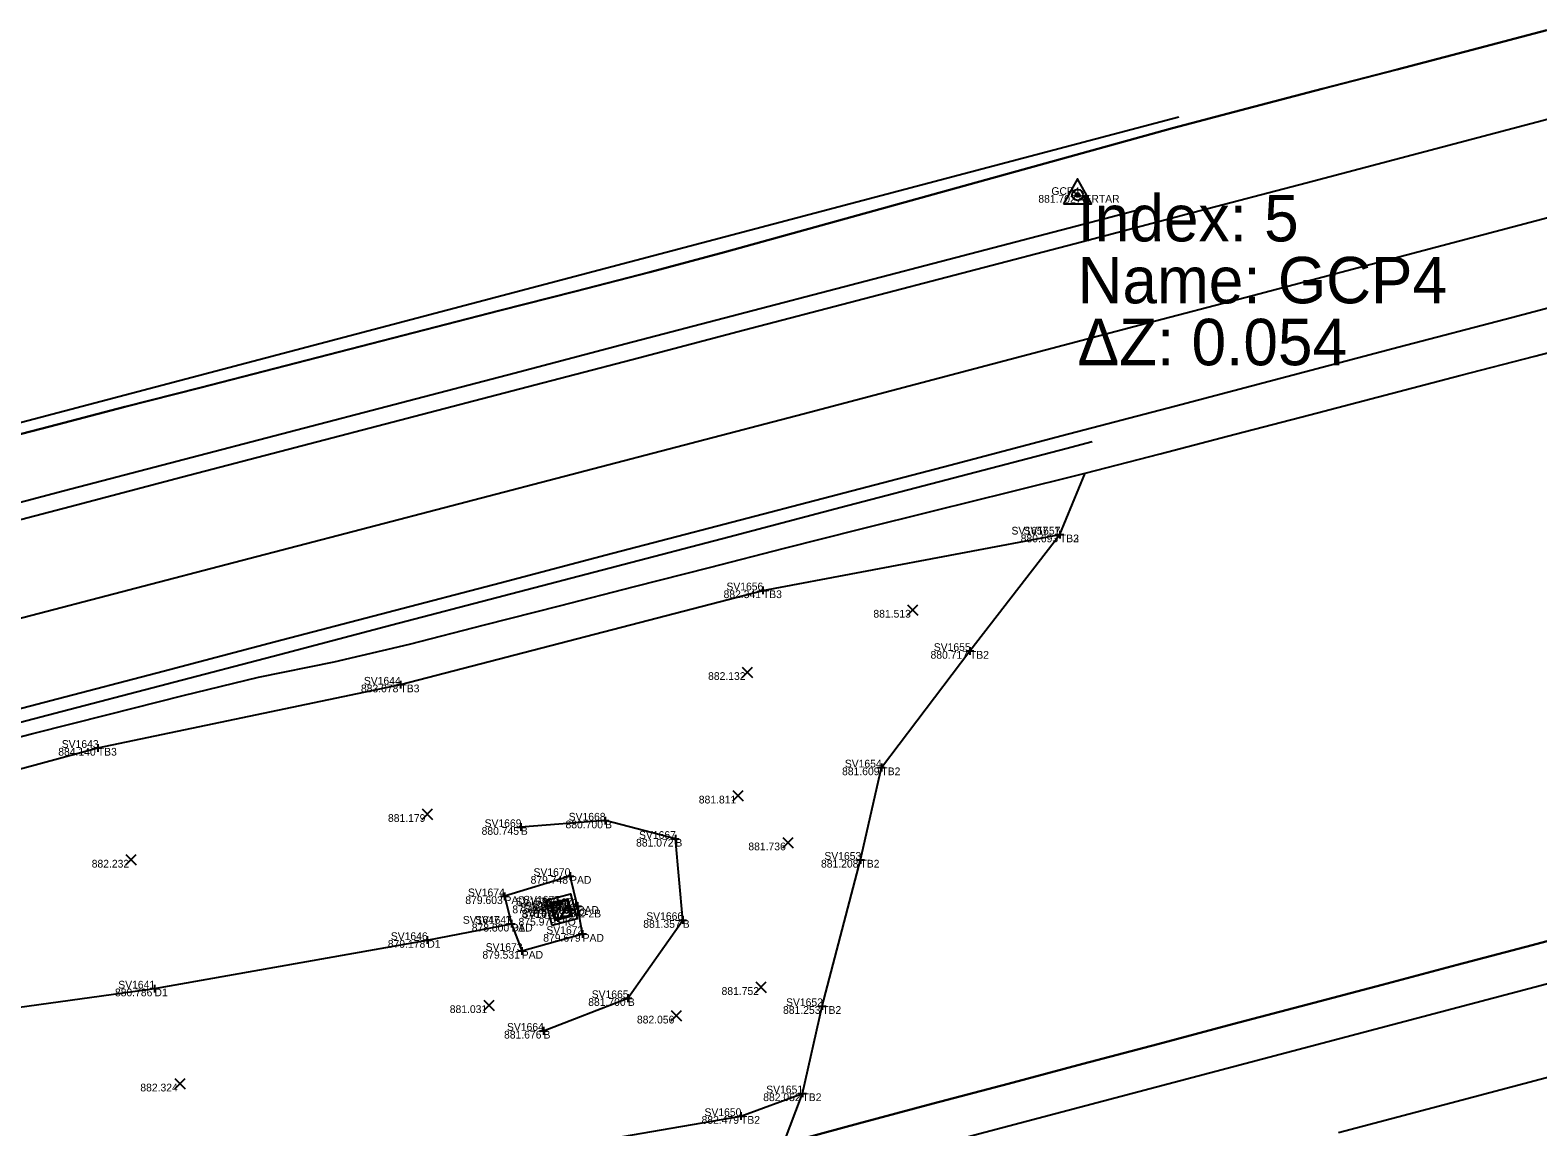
# Model space of a CAD drawing. Extents: x 2125299 to 2129212, y 713100 to 714300.
# Drawn here: x 2127838.8 to 2128033.5, y 713888.4 to 714030.1 of the extents above; entities that cross this region are included whole.
import ezdxf

# ---------------------------------------------------------------- set-up
doc = ezdxf.new("R2010")
doc.units = 0
for name, color, linetype in [('_CIVIL_CONSTRUCTION', 7, 'Continuous'), ('DR_X_Ditch', 7, 'Continuous'), ('DT_X_Terrain_Boundary', 7, 'Continuous'), ('DT_X_Void', 7, 'Continuous'), ('PV_X_EOP', 7, 'Continuous'), ('PV_X_Shoulder_Rumble_Strip', 7, 'Continuous'), ('RD_X_Concrete_Pad', 7, 'Continuous'), ('RW_P_Esmt_TMP', 7, 'Continuous'), ('RW_X_CL_100_Bearings', 7, 'Continuous'), ('RW_X_CL_100_Cardinal_Points', 7, 'Continuous'), ('RW_X_Esmt_CH', 7, 'Continuous'), ('RW_X_Fee_WL', 7, 'Continuous'), ('SC_Scratch1', 7, 'Continuous'), ('SC_Scratch2', 7, 'Continuous'), ('SV_P_Aerial_Targets', 7, 'Continuous'), ('SV_X_Break_Lines', 7, 'Continuous'), ('SV_X_Mon_Cells_Found', 7, 'Continuous'), ('SV_X_Text_Comment', 7, 'Continuous'), ('SV_X_Text_Elevation', 7, 'Continuous'), ('SV_X_Top_of_Bank', 7, 'Continuous')]:
    doc.layers.add(name, color=color, linetype=linetype)

msp = doc.modelspace()

# ---------------------------------------------------------------- linework, layer by layer
at = {"layer": '_CIVIL_CONSTRUCTION'}
msp.add_line((2127974.08, 714008.8), (2127974.08, 714008.8), dxfattribs=at)
for points in [[(2127837.05, 713953.98), (2127851.56, 713957.77), (2127866.07, 713961.56), (2127880.59, 713965.36), (2127895.1, 713969.15), (2127909.61, 713972.94), (2127924.13, 713976.73), (2127938.64, 713980.53), (2127953.14, 713984.36), (2127967.64, 713988.18), (2127982.15, 713992.01), (2127996.65, 713995.83), (2128011.16, 713999.66), (2128025.66, 714003.48), (2128040.17, 714007.31)], [(2128007.76, 713887.68), (2128022.26, 713891.52), (2128036.76, 713895.35)]]:
    msp.add_lwpolyline(points, dxfattribs=at)
msp.add_circle((2127974.08, 714008.8), 0.25, dxfattribs=at)
at = {"layer": 'DR_X_Ditch'}
msp.add_lwpolyline([(2127104.46, 713722.2), (2127161.17, 713739.36), (2127224.94, 713755.07), (2127279.95, 713770.84), (2127341.71, 713787.57), (2127396.23, 713800.84), (2127459.54, 713814.71), (2127515.88, 713829.56), (2127633.42, 713858.63), (2127660.82, 713865.77), (2127680.17, 713870.09), (2127707.74, 713876.68), (2127734.62, 713883.6), (2127780.13, 713896.01), (2127811.25, 713900.24), (2127854.87, 713906.28), (2127890.1, 713912.55), (2127900.96, 713914.65)], dxfattribs=at)
at = {"layer": 'DT_X_Terrain_Boundary'}
msp.add_lwpolyline([(2128034.69, 714030.09), (2128025.02, 714027.56), (2128015.34, 714025.02), (2128005.67, 714022.49), (2127996, 714019.95), (2127986.32, 714017.42), (2127976.68, 714014.76), (2127967.04, 714012.09), (2127957.41, 714009.42), (2127947.77, 714006.75), (2127938.13, 714004.08), (2127928.5, 714001.41), (2127918.83, 713998.84), (2127909.15, 713996.35), (2127899.46, 713993.86), (2127889.78, 713991.37), (2127880.09, 713988.88), (2127870.41, 713986.39), (2127860.72, 713983.9), (2127851.04, 713981.41), (2127841.36, 713978.9), (2127831.68, 713976.38)], dxfattribs=at)
at = {"layer": 'DT_X_Void'}
msp.add_lwpolyline([(2128042.43, 713914.46), (2128032.77, 713911.9), (2128023.1, 713909.34), (2128013.43, 713906.78), (2128003.77, 713904.22), (2127994.1, 713901.66), (2127984.43, 713899.1), (2127974.77, 713896.54), (2127965.1, 713893.98), (2127955.43, 713891.42), (2127945.77, 713888.86), (2127936.12, 713886.22), (2127938.55, 713892.74), (2127941.1, 713904.01), (2127946.04, 713922.91), (2127948.74, 713934.84), (2127960.18, 713949.89), (2127971.8, 713964.93), (2127975.06, 713972.85), (2127984.74, 713975.36), (2127994.42, 713977.88), (2128004.09, 713980.41), (2128013.77, 713982.93), (2128023.45, 713985.46), (2128033.12, 713987.98), (2128042.8, 713990.51)], dxfattribs=at)
at = {"layer": 'PV_X_EOP'}
for points in [[(2127831.68, 713976.38), (2127841.36, 713978.9), (2127851.04, 713981.41), (2127860.72, 713983.9), (2127870.41, 713986.39), (2127880.09, 713988.88), (2127889.78, 713991.37), (2127899.46, 713993.86), (2127909.15, 713996.35), (2127918.83, 713998.84), (2127928.5, 714001.41), (2127938.13, 714004.08), (2127947.77, 714006.75), (2127957.41, 714009.42), (2127967.04, 714012.09), (2127976.68, 714014.76), (2127986.32, 714017.42), (2127996, 714019.95), (2128005.67, 714022.49), (2128015.34, 714025.02), (2128025.02, 714027.56), (2128034.69, 714030.09)], [(2127829.49, 713936.72), (2127839.17, 713939.25), (2127848.87, 713941.69), (2127858.56, 713944.13), (2127868.28, 713946.49), (2127878.08, 713948.47), (2127887.81, 713950.79), (2127897.5, 713953.26), (2127907.19, 713955.74), (2127916.87, 713958.21), (2127926.56, 713960.69), (2127936.25, 713963.16), (2127945.95, 713965.61), (2127955.65, 713968.02), (2127965.36, 713970.44), (2127975.06, 713972.85), (2127984.74, 713975.36), (2127994.42, 713977.88), (2128004.09, 713980.41), (2128013.77, 713982.93), (2128023.45, 713985.46), (2128033.12, 713987.98), (2128042.8, 713990.51)], [(2127936.12, 713886.22), (2127945.77, 713888.86), (2127955.43, 713891.42), (2127965.1, 713893.98), (2127974.77, 713896.54), (2127984.43, 713899.1), (2127994.1, 713901.66), (2128003.77, 713904.22), (2128013.43, 713906.78), (2128023.1, 713909.34), (2128032.77, 713911.9), (2128042.43, 713914.46)]]:
    msp.add_lwpolyline(points, dxfattribs=at)
at = {"layer": 'PV_X_Shoulder_Rumble_Strip'}
for points in [[(2127654.66, 713921.17), (2127669.16, 713925.01), (2127683.66, 713928.84), (2127698.17, 713932.65), (2127712.67, 713936.44), (2127727.18, 713940.24), (2127741.69, 713944.04), (2127756.2, 713947.83), (2127770.71, 713951.63), (2127785.22, 713955.43), (2127799.73, 713959.22), (2127814.23, 713963.02), (2127828.74, 713966.81), (2127843.25, 713970.61), (2127857.76, 713974.41), (2127872.26, 713978.2), (2127886.77, 713982), (2127901.28, 713985.8), (2127915.79, 713989.59), (2127930.3, 713993.39), (2127944.81, 713997.19), (2127959.31, 714000.98), (2127973.82, 714004.78), (2127983.03, 714007.2)], [(2127653.45, 713892.3), (2127667.94, 713896.15), (2127682.44, 713899.99), (2127696.93, 713903.84), (2127711.44, 713907.65), (2127725.95, 713911.45), (2127740.46, 713915.25), (2127754.96, 713919.05), (2127769.47, 713922.85), (2127783.98, 713926.65), (2127798.49, 713930.45), (2127812.99, 713934.25), (2127827.5, 713938.05), (2127842.01, 713941.85), (2127856.51, 713945.65), (2127871.02, 713949.45), (2127885.53, 713953.25), (2127900.03, 713957.05), (2127914.54, 713960.85), (2127929.05, 713964.65), (2127943.56, 713968.45), (2127958.06, 713972.25), (2127972.57, 713976.05), (2127975.95, 713976.94)]]:
    msp.add_lwpolyline(points, dxfattribs=at)
at = {"layer": 'RD_X_Concrete_Pad'}
msp.add_lwpolyline([(2127900.07, 713918.2), (2127900.96, 713914.65), (2127902.3, 713911.14), (2127910.16, 713913.33), (2127909.51, 713916.94), (2127908.54, 713920.82)], close=True, dxfattribs=at)
at = {"layer": 'RW_X_CL_100_Bearings'}
for p, q in [((2127907, 713918.09), (2127907, 713918.09)), ((2127907.17, 713917.44), (2127907.17, 713917.44)), ((2127908.39, 713916.72), (2127908.39, 713916.72)), ((2127906.45, 713916.22), (2127906.45, 713916.22)), ((2127907.42, 713916.47), (2127907.42, 713916.47)), ((2127907.42, 713916.47), (2127907.42, 713916.47)), ((2127907.42, 713916.47), (2127907.42, 713916.47)), ((2127907.67, 713915.5), (2127907.67, 713915.5)), ((2127907.84, 713914.86), (2127907.84, 713914.86))]:
    msp.add_line(p, q, dxfattribs=at)
at = {"layer": 'RW_X_CL_100_Cardinal_Points'}
for p, q in [((2127905.68, 713917.01), (2127906.68, 713917.01)), ((2127906.18, 713917.51), (2127906.18, 713916.51)), ((2127906.18, 713917.01), (2127906.18, 713917.01)), ((2127906.68, 713917.25), (2127907.68, 713917.25)), ((2127907.18, 713917.75), (2127907.18, 713916.75)), ((2127907.18, 713917.25), (2127907.18, 713917.25)), ((2127907.9, 713916.62), (2127908.9, 713916.62)), ((2127908.4, 713917.12), (2127908.4, 713916.12)), ((2127908.4, 713916.62), (2127908.4, 713916.62)), ((2127906.47, 713915.41), (2127907.47, 713915.41)), ((2127906.97, 713915.91), (2127906.97, 713914.91)), ((2127906.97, 713915.41), (2127906.97, 713915.41))]:
    msp.add_line(p, q, dxfattribs=at)
at = {"layer": 'SC_Scratch1'}
msp.add_lwpolyline([(2127987.17, 714018.86), (2127920.93, 714001.38), (2127683.07, 713938.63), (2127539.5, 713900.27), (2127439.69, 713873.74), (2127381.79, 713858.41), (2127328.47, 713844.31), (2127152.7, 713796.25), (2127072.88, 713773.07)], dxfattribs=at)
at = {"layer": 'SC_Scratch2'}
for points in [[(2127829.47, 713964.78), (2127843.98, 713968.57), (2127858.49, 713972.37), (2127873, 713976.17), (2127887.51, 713979.97), (2127902.02, 713983.76), (2127916.54, 713987.56), (2127931.05, 713991.36), (2127945.56, 713995.16), (2127960.07, 713998.95), (2127974.58, 714002.75), (2127989.09, 714006.56), (2128003.59, 714010.38), (2128018.1, 714014.21), (2128032.6, 714018.03), (2128047.11, 714021.86)], [(2127826.97, 713939.7), (2127841.48, 713943.5), (2127855.99, 713947.3), (2127870.5, 713951.1), (2127885.01, 713954.9), (2127899.52, 713958.71), (2127914.03, 713962.51), (2127928.55, 713966.31), (2127943.06, 713970.11), (2127957.57, 713973.91), (2127972.08, 713977.71), (2127986.58, 713981.52), (2128001.09, 713985.35), (2128015.59, 713989.17), (2128030.1, 713992.99), (2128044.6, 713996.81)], [(2127957.55, 713886.51), (2127972.05, 713890.34), (2127986.55, 713894.17), (2128001.05, 713898), (2128015.56, 713901.84), (2128030.06, 713905.67), (2128044.56, 713909.5)]]:
    msp.add_lwpolyline(points, dxfattribs=at)
at = {"layer": 'SV_P_Aerial_Targets'}
msp.add_line((2127974.08, 714008.8), (2127974.08, 714008.8), dxfattribs=at)
msp.add_lwpolyline([(2127972.28, 714007.65), (2127975.88, 714007.65), (2127974.08, 714010.87)], close=True, dxfattribs=at)
msp.add_lwpolyline([(2127972.28, 714007.65), (2127975.88, 714007.65), (2127974.08, 714010.87)], close=True, dxfattribs=at)
for radius in [0.7, 0.7, 0.16, 0.16]:
    msp.add_circle((2127974.08, 714008.8), radius, dxfattribs=at)
at = {"layer": 'SV_X_Break_Lines'}
msp.add_lwpolyline([(2127905.11, 713900.82), (2127916, 713905.04), (2127923.09, 713915.13), (2127922.14, 713925.62), (2127913.06, 713927.98), (2127902.18, 713927.14)], dxfattribs=at)
at = {"layer": 'SV_X_Mon_Cells_Found'}
for p, q in [((2127971.8, 713965.43), (2127971.8, 713964.43)), ((2127971.8, 713965.43), (2127971.8, 713964.43)), ((2127971.3, 713964.93), (2127972.3, 713964.93)), ((2127971.3, 713964.93), (2127972.3, 713964.93)), ((2127971.8, 713964.93), (2127971.8, 713964.93)), ((2127971.8, 713964.93), (2127971.8, 713964.93)), ((2127932.94, 713957.72), (2127933.94, 713957.72)), ((2127933.44, 713958.22), (2127933.44, 713957.22)), ((2127933.44, 713957.72), (2127933.44, 713957.72)), ((2127959.68, 713949.89), (2127960.68, 713949.89)), ((2127960.18, 713950.39), (2127960.18, 713949.39)), ((2127960.18, 713949.89), (2127960.18, 713949.89)), ((2127886.63, 713946.04), (2127886.63, 713945.04)), ((2127886.13, 713945.54), (2127887.13, 713945.54)), ((2127886.63, 713945.54), (2127886.63, 713945.54)), ((2127847.05, 713937.37), (2127848.05, 713937.37)), ((2127847.55, 713937.87), (2127847.55, 713936.87)), ((2127847.55, 713937.37), (2127847.55, 713937.37)), ((2127948.24, 713934.84), (2127949.24, 713934.84)), ((2127948.74, 713935.34), (2127948.74, 713934.34)), ((2127948.74, 713934.84), (2127948.74, 713934.84)), ((2127913.06, 713928.48), (2127913.06, 713927.48)), ((2127901.68, 713927.14), (2127902.68, 713927.14)), ((2127902.18, 713927.64), (2127902.18, 713926.64)), ((2127902.18, 713927.14), (2127902.18, 713927.14)), ((2127912.56, 713927.98), (2127913.56, 713927.98)), ((2127913.06, 713927.98), (2127913.06, 713927.98)), ((2127921.64, 713925.62), (2127922.64, 713925.62)), ((2127922.14, 713926.12), (2127922.14, 713925.12)), ((2127922.14, 713925.62), (2127922.14, 713925.62)), ((2127945.54, 713922.91), (2127946.54, 713922.91)), ((2127946.04, 713923.41), (2127946.04, 713922.41)), ((2127946.04, 713922.91), (2127946.04, 713922.91)), ((2127908.04, 713920.82), (2127909.04, 713920.82)), ((2127908.54, 713921.32), (2127908.54, 713920.32)), ((2127908.54, 713920.82), (2127908.54, 713920.82)), ((2127900.07, 713918.7), (2127900.07, 713917.7)), ((2127899.57, 713918.2), (2127900.57, 713918.2)), ((2127900.07, 713918.2), (2127900.07, 713918.2)), ((2127909.01, 713916.94), (2127910.01, 713916.94)), ((2127909.51, 713917.44), (2127909.51, 713916.44)), ((2127909.51, 713916.94), (2127909.51, 713916.94)), ((2127900.46, 713914.65), (2127901.46, 713914.65)), ((2127900.46, 713914.65), (2127901.46, 713914.65)), ((2127900.96, 713915.15), (2127900.96, 713914.15)), ((2127900.96, 713915.15), (2127900.96, 713914.15)), ((2127900.96, 713914.65), (2127900.96, 713914.65)), ((2127900.96, 713914.65), (2127900.96, 713914.65)), ((2127922.59, 713915.13), (2127923.59, 713915.13)), ((2127923.09, 713915.63), (2127923.09, 713914.63)), ((2127923.09, 713915.13), (2127923.09, 713915.13)), ((2127890.1, 713913.05), (2127890.1, 713912.05)), ((2127909.66, 713913.33), (2127910.66, 713913.33)), ((2127910.16, 713913.83), (2127910.16, 713912.83)), ((2127910.16, 713913.33), (2127910.16, 713913.33)), ((2127889.6, 713912.55), (2127890.6, 713912.55)), ((2127890.1, 713912.55), (2127890.1, 713912.55)), ((2127901.8, 713911.14), (2127902.8, 713911.14)), ((2127902.3, 713911.64), (2127902.3, 713910.64)), ((2127902.3, 713911.14), (2127902.3, 713911.14)), ((2127854.37, 713906.28), (2127855.37, 713906.28)), ((2127854.87, 713906.78), (2127854.87, 713905.78)), ((2127854.87, 713906.28), (2127854.87, 713906.28)), ((2127915.5, 713905.04), (2127916.5, 713905.04)), ((2127916, 713905.54), (2127916, 713904.54)), ((2127916, 713905.04), (2127916, 713905.04)), ((2127940.6, 713904.01), (2127941.6, 713904.01)), ((2127941.1, 713904.51), (2127941.1, 713903.51)), ((2127941.1, 713904.01), (2127941.1, 713904.01)), ((2127905.11, 713901.32), (2127905.11, 713900.32)), ((2127904.61, 713900.82), (2127905.61, 713900.82)), ((2127905.11, 713900.82), (2127905.11, 713900.82)), ((2127938.55, 713893.24), (2127938.55, 713892.24)), ((2127938.05, 713892.74), (2127939.05, 713892.74)), ((2127938.55, 713892.74), (2127938.55, 713892.74)), ((2127930.11, 713889.81), (2127931.11, 713889.81)), ((2127930.61, 713890.31), (2127930.61, 713889.31)), ((2127930.61, 713889.81), (2127930.61, 713889.81))]:
    msp.add_line(p, q, dxfattribs=at)
at = {"layer": 'SV_X_Text_Comment'}
for p, q in [((2127906.18, 713916.69), (2127906.63, 713917.45)), ((2127906.46, 713915.59), (2127907.72, 713917.74)), ((2127907.18, 713915.23), (2127908.39, 713917.29)), ((2127908.27, 713915.51), (2127908.67, 713916.2))]:
    msp.add_line(p, q, dxfattribs=at)
for points in [[(2127905.39, 713917.67), (2127908.61, 713918.5), (2127909.45, 713915.28), (2127906.22, 713914.44)], [(2127906.02, 713917.29), (2127908.24, 713917.87), (2127908.81, 713915.65), (2127906.6, 713915.08)], [(2127906.2, 713917.19), (2127908.13, 713917.69), (2127908.64, 713915.76), (2127906.7, 713915.25)]]:
    msp.add_lwpolyline(points, close=True, dxfattribs=at)
at = {"layer": 'SV_X_Text_Elevation'}
for p, q in [((2127952.11, 713954.53), (2127953.44, 713955.87)), ((2127952.11, 713955.87), (2127953.44, 713954.53)), ((2127930.77, 713946.48), (2127932.1, 713947.82)), ((2127930.77, 713947.82), (2127932.1, 713946.48)), ((2127929.57, 713930.52), (2127930.91, 713931.86)), ((2127929.57, 713931.86), (2127930.91, 713930.52)), ((2127889.44, 713928.14), (2127890.77, 713929.48)), ((2127889.44, 713929.48), (2127890.77, 713928.14)), ((2127936, 713924.47), (2127937.33, 713925.81)), ((2127936, 713925.81), (2127937.33, 713924.47)), ((2127851.17, 713922.25), (2127852.5, 713923.58)), ((2127851.17, 713923.58), (2127852.5, 713922.25)), ((2127932.51, 713905.79), (2127933.84, 713907.13)), ((2127932.51, 713907.13), (2127933.84, 713905.79)), ((2127897.41, 713903.45), (2127898.75, 713904.79)), ((2127897.41, 713904.79), (2127898.75, 713903.45)), ((2127921.61, 713902.1), (2127922.94, 713903.44)), ((2127921.61, 713903.44), (2127922.94, 713902.1)), ((2127857.5, 713893.32), (2127858.83, 713894.66)), ((2127857.5, 713894.66), (2127858.83, 713893.32))]:
    msp.add_line(p, q, dxfattribs=at)
at = {"layer": 'SV_X_Top_of_Bank'}
for points in [[(2127101.4, 713732.92), (2127157.86, 713749.53), (2127222.47, 713767.6), (2127276.61, 713783.01), (2127338.05, 713802.99), (2127391.69, 713816.17), (2127455.85, 713833.15), (2127455.8, 713833.25), (2127510.11, 713848.18), (2127573.33, 713861.42), (2127627.49, 713877.76), (2127656.95, 713884.76), (2127703.68, 713898.62), (2127726.61, 713904.03), (2127772.75, 713915.63), (2127805.28, 713925.94), (2127847.55, 713937.37), (2127886.63, 713945.54), (2127933.44, 713957.72), (2127971.8, 713964.93)], [(2127691.05, 713857.86), (2127708.64, 713865.58), (2127737.13, 713873.46), (2127762.81, 713869.75), (2127785.71, 713871.04), (2127815.54, 713873.93), (2127860.68, 713880.21), (2127901.34, 713884.74), (2127930.61, 713889.81), (2127938.55, 713892.74), (2127941.1, 713904.01), (2127946.04, 713922.91), (2127948.74, 713934.84), (2127960.18, 713949.89), (2127971.8, 713964.93)]]:
    msp.add_lwpolyline(points, dxfattribs=at)

# ---------------------------------------------------------------- texts
at = {"layer": '_CIVIL_CONSTRUCTION'}
for s, p in [('Index: 5', (2127974.08, 714002.8)), ('Name: GCP4', (2127974.08, 713994.8)), ('ΔZ: 0.054', (2127974.08, 713986.8))]:
    msp.add_text(s, height=6, dxfattribs=at).set_placement(p)
at = {"layer": 'RW_P_Esmt_TMP'}
for s, p in [('AERTAR', (2127974.08, 714007.8)), ('AERTAR', (2127974.08, 714007.8)), ('TB3', (2127971.8, 713963.93)), ('TB2', (2127971.8, 713963.93)), ('TB3', (2127933.44, 713956.72)), ('TB2', (2127960.18, 713948.89)), ('TB3', (2127886.63, 713944.55)), ('TB3', (2127847.55, 713936.37)), ('TB2', (2127948.74, 713933.84)), ('B', (2127902.18, 713926.14)), ('B', (2127913.06, 713926.98)), ('B', (2127922.14, 713924.62)), ('TB2', (2127946.04, 713921.91)), ('PAD', (2127908.54, 713919.82)), ('PAD', (2127900.07, 713917.2)), ('PIO', (2127906.18, 713916.01)), ('PIO', (2127907.18, 713916.25)), ('PIO', (2127908.4, 713915.62)), ('PAD', (2127909.51, 713915.94)), ('D1', (2127900.96, 713913.65)), ('PAD', (2127900.96, 713913.65)), ('PIO', (2127906.97, 713914.41)), ('CB-2-2B', (2127907.42, 713915.47)), ('B', (2127923.09, 713914.13)), ('PAD', (2127910.16, 713912.33)), ('D1', (2127890.1, 713911.55)), ('PAD', (2127902.3, 713910.14)), ('D1', (2127854.87, 713905.28)), ('B', (2127916, 713904.04)), ('TB2', (2127941.1, 713903.01)), ('B', (2127905.11, 713899.82)), ('TB2', (2127938.55, 713891.74)), ('TB2', (2127930.61, 713888.81))]:
    msp.add_text(s, height=1, dxfattribs=at).set_placement(p)
at = {"layer": 'RW_X_Esmt_CH'}
for s, p in [('GCP4', (2127970.7, 714008.8)), ('GCP4', (2127970.7, 714008.8)), ('SV1657_1', (2127965.54, 713964.93)), ('SV1657', (2127967.1, 713964.93)), ('SV1656', (2127928.73, 713957.72)), ('SV1655', (2127955.51, 713949.89)), ('SV1644', (2127881.91, 713945.54)), ('SV1643', (2127842.89, 713937.37)), ('SV1654', (2127944.02, 713934.84)), ('SV1668', (2127908.36, 713927.98)), ('SV1669', (2127897.5, 713927.14)), ('SV1667', (2127917.44, 713925.62)), ('SV1653', (2127941.38, 713922.91)), ('SV1670', (2127903.82, 713920.82)), ('SV1674', (2127895.35, 713918.2)), ('SV1676', (2127901.48, 713917.01)), ('SV1677', (2127902.48, 713917.25)), ('SV1675', (2127902.75, 713916.47)), ('SV1679', (2127903.72, 713916.62)), ('SV1671', (2127904.83, 713916.94)), ('SV1647_1', (2127894.69, 713914.65)), ('SV1647', (2127896.26, 713914.65)), ('SV1678', (2127902.27, 713915.41)), ('SV1666', (2127918.38, 713915.13)), ('SV1646', (2127885.39, 713912.55)), ('SV1672', (2127905.48, 713913.33)), ('SV1673', (2127897.64, 713911.14)), ('SV1641', (2127850.19, 713906.28)), ('SV1665', (2127911.33, 713905.04)), ('SV1652', (2127936.43, 713904.01)), ('SV1664', (2127900.39, 713900.82)), ('SV1651', (2127933.87, 713892.74)), ('SV1650', (2127925.9, 713889.81))]:
    msp.add_text(s, height=1, dxfattribs=at).set_placement(p)
at = {"layer": 'RW_X_Fee_WL'}
for s, p in [('881.702', (2127969.01, 714007.8)), ('881.702', (2127969.01, 714007.8)), ('880.693', (2127966.73, 713963.93)), ('880.693', (2127966.73, 713963.93)), ('882.341', (2127928.36, 713956.72)), ('881.513', (2127947.71, 713954.2)), ('880.717', (2127955.09, 713948.89)), ('882.132', (2127926.36, 713946.15)), ('883.078', (2127881.53, 713944.55)), ('884.140', (2127842.44, 713936.37)), ('881.609', (2127943.66, 713933.84)), ('881.811', (2127925.16, 713930.19)), ('881.179', (2127885.02, 713927.81)), ('880.745', (2127897.11, 713926.14)), ('880.700', (2127907.95, 713926.98)), ('881.072', (2127917.06, 713924.62)), ('881.736', (2127931.56, 713924.14)), ('882.232', (2127846.76, 713921.91)), ('881.208', (2127940.94, 713921.91)), ('879.748', (2127903.44, 713919.82)), ('879.603', (2127895.01, 713917.2)), ('875.946', (2127901.08, 713916.01)), ('875.853', (2127902.11, 713916.25)), ('875.572', (2127903.33, 713915.62)), ('878.958', (2127904.41, 713915.94)), ('878.800', (2127895.84, 713913.65)), ('878.800', (2127895.84, 713913.65)), ('875.979', (2127901.88, 713914.41)), ('878.786', (2127902.31, 713915.47)), ('881.357', (2127917.99, 713914.13)), ('879.679', (2127905.07, 713912.33)), ('879.178', (2127885, 713911.55)), ('879.531', (2127897.22, 713910.14)), ('880.786', (2127849.76, 713905.28)), ('881.700', (2127910.88, 713904.04)), ('881.752', (2127928.1, 713905.46)), ('881.031', (2127893, 713903.12)), ('881.253', (2127936.04, 713903.01)), ('882.056', (2127917.17, 713901.77)), ('881.676', (2127900.01, 713899.82)), ('882.324', (2127853.04, 713892.99)), ('882.052', (2127933.48, 713891.74)), ('882.479', (2127925.52, 713888.81))]:
    msp.add_text(s, height=1, dxfattribs=at).set_placement(p)

doc.saveas('drawing.dxf')
